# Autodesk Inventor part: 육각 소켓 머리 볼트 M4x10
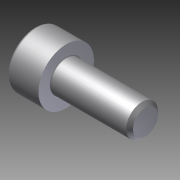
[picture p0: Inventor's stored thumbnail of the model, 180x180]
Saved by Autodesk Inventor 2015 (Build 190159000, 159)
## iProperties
Created: 2024-12
Part Number: 육각 소켓 머리 볼트 M4x10
Material: 일반
Document SubType Name: Modeling
Designer: 10401
Density: 1 g/cm^3
Appearance: 기본값
Author: 10401
Author: jhkim
Description: 6각머리 태핑 나사
Creation Date: 2024-11-28
Sending System: Autodesk Inventor 2025
Preprocessor: ST-DEVELOPER v20
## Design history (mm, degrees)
node "육각 소켓 머리 볼트 M4x101"
body "Solid1"
node "기준1"
